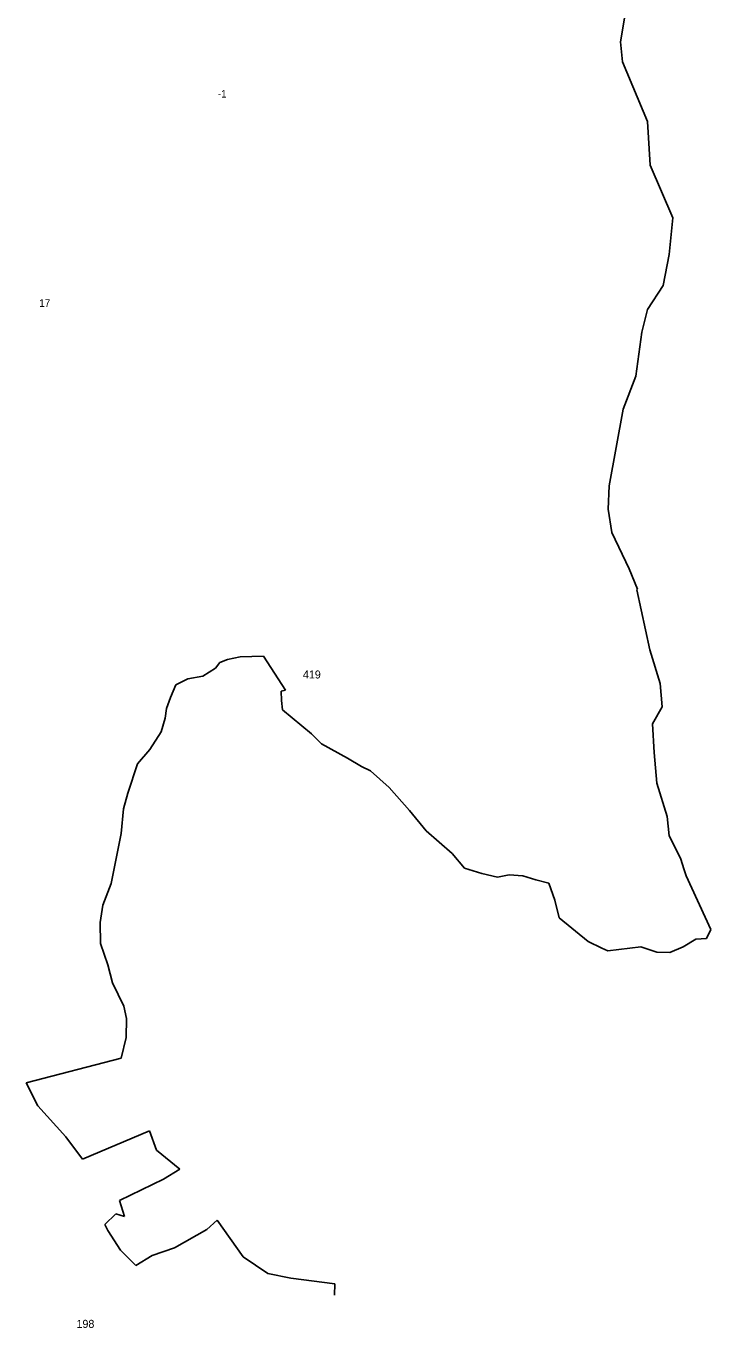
# Model space of a CAD drawing. Extents: x -779790 to -775735, y -971779 to -967735.
# Drawn here: x -777841 to -776814, y -971679 to -969727 of the extents above; entities that cross this region are included whole.
import ezdxf

# ---------------------------------------------------------------- set-up
doc = ezdxf.new("R2010")
doc.units = 0
for name, color, linetype in [('Vrstva 1', 7, 'Continuous'), ('Vrstva 15', 7, 'Continuous'), ('Vrstva 24', 7, 'Continuous')]:
    doc.layers.add(name, color=color, linetype=linetype)

msp = doc.modelspace()

# ---------------------------------------------------------------- linework, layer by layer
at = {"layer": 'Vrstva 1'}
for p, q in [((-776941.52, -969703.14), (-776949.64, -969750.41)), ((-776949.64, -969750.41), (-776946.93, -969780.45)), ((-776946.93, -969780.45), (-776909.02, -969870.08)), ((-776909.02, -969870.08), (-776905.09, -969935.33)), ((-776905.09, -969935.33), (-776871.35, -970014.61)), ((-776871.35, -970014.61), (-776876.53, -970069.51)), ((-776876.53, -970069.51), (-776885.88, -970115.8)), ((-776885.88, -970115.8), (-776909.27, -970151.75)), ((-776909.27, -970151.75), (-776917.65, -970185.98)), ((-776917.65, -970185.98), (-776926.76, -970251.71)), ((-776926.76, -970251.71), (-776945.96, -970301.2)), ((-776945.96, -970301.2), (-776966.89, -970416.18)), ((-776966.89, -970416.18), (-776968.36, -970451.39)), ((-776968.36, -970451.39), (-776962.94, -970486.6)), ((-776962.94, -970486.6), (-776936.84, -970541.01)), ((-776936.84, -970541.01), (-776924.04, -970571.29)), ((-776925.18, -970572.6), (-776924.04, -970571.29)), ((-777557.11, -970690), (-777550.31, -970681.51)), ((-777550.31, -970681.51), (-777538.76, -970677.09)), ((-777538.76, -970677.09), (-777520.06, -970673.01)), ((-777520.06, -970673.01), (-777485.06, -970671.99)), ((-777485.06, -970671.99), (-777452.1, -970722.97)), ((-777616.58, -970714.81), (-777598.57, -970705.98)), ((-777598.57, -970705.98), (-777575.8, -970701.9)), ((-777575.8, -970701.9), (-777557.11, -970690)), ((-777624.4, -970733.85), (-777616.58, -970714.81)), ((-777452.1, -970722.97), (-777458.39, -970724.55)), ((-777458.39, -970724.55), (-777457.87, -970738.27)), ((-777630.52, -970750.5), (-777624.4, -970733.85)), ((-777457.87, -970738.27), (-777456.51, -970752.2)), ((-777638.34, -970785.17), (-777632.22, -970764.77)), ((-777632.22, -970764.77), (-777630.52, -970750.5)), ((-777456.51, -970752.2), (-777413.01, -970788.57)), ((-777655.33, -970812.02), (-777638.34, -970785.17)), ((-777413.01, -970788.57), (-777398.06, -970803.18)), ((-777398.06, -970803.18), (-777358.97, -970824.93)), ((-777674.02, -970833.43), (-777655.33, -970812.02)), ((-777358.97, -970824.93), (-777337.9, -970837.51)), ((-777688.3, -970877.27), (-777674.02, -970833.43)), ((-777337.9, -970837.51), (-777324.65, -970843.96)), ((-777324.65, -970843.96), (-777296.78, -970868.77)), ((-777694.76, -970901.06), (-777688.3, -970877.27)), ((-777296.78, -970868.77), (-777265.85, -970903.44)), ((-777698.16, -970937.76), (-777694.76, -970901.06)), ((-777265.85, -970903.44), (-777241.04, -970934.03)), ((-777713.45, -971012.87), (-777698.16, -970937.76)), ((-777241.04, -970934.03), (-777202.29, -970968.01)), ((-777202.29, -970968.01), (-777183.6, -970989.77)), ((-777183.6, -970989.77), (-777157.77, -970997.92)), ((-777157.77, -970997.92), (-777134.32, -971003.36)), ((-777134.32, -971003.36), (-777116.65, -970999.96)), ((-777116.65, -970999.96), (-777095.91, -971001.32)), ((-777095.91, -971001.32), (-777076.54, -971007.44)), ((-777725.69, -971045.16), (-777713.45, -971012.87)), ((-777076.54, -971007.44), (-777057.17, -971012.2)), ((-777057.17, -971012.2), (-777048.33, -971038.03)), ((-777048.33, -971038.03), (-777041.88, -971064.2)), ((-777729.77, -971071.33), (-777725.69, -971045.16)), ((-777729.09, -971102.94), (-777729.77, -971071.33)), ((-777041.88, -971064.2), (-776998.03, -971099.54)), ((-777718.55, -971134.55), (-777729.09, -971102.94)), ((-777711.41, -971161.74), (-777718.55, -971134.55)), ((-777694.42, -971196.74), (-777711.41, -971161.74)), ((-777690.34, -971215.44), (-777694.42, -971196.74)), ((-777690.69, -971243.98), (-777690.34, -971215.44)), ((-777698.16, -971274.57), (-777690.69, -971243.98)), ((-777840.91, -971311.58), (-777698.16, -971274.57)), ((-777823.24, -971346.25), (-777840.91, -971311.58)), ((-777781.43, -971392.85), (-777823.24, -971346.25)), ((-777655.68, -971383.67), (-777756.28, -971426.49)), ((-777645.14, -971412.9), (-777655.68, -971383.67)), ((-777756.28, -971426.49), (-777781.43, -971392.85)), ((-777610.48, -971441.44), (-777645.14, -971412.9)), ((-777634.61, -971456.06), (-777610.48, -971441.44)), ((-777700.88, -971488), (-777634.61, -971456.06)), ((-777693.41, -971512.47), (-777700.88, -971488)), ((-777722.63, -971524.37), (-777706.32, -971508.4)), ((-777706.32, -971508.4), (-777693.41, -971512.47)), ((-777718.22, -971533.21), (-777722.63, -971524.37)), ((-777554.41, -971517.57), (-777570.04, -971531.85)), ((-777515.32, -971572.97), (-777554.41, -971517.57)), ((-777699.18, -971562.77), (-777718.22, -971533.21)), ((-777570.04, -971531.85), (-777618.3, -971559.38)), ((-777676.41, -971585.55), (-777699.18, -971562.77)), ((-777618.3, -971559.38), (-777651.94, -971570.59)), ((-777651.94, -971570.59), (-777676.41, -971585.55)), ((-777478.28, -971597.78), (-777515.32, -971572.97)), ((-777443.95, -971604.92), (-777478.28, -971597.78)), ((-777378.02, -971613.42), (-777443.95, -971604.92)), ((-777378.7, -971630.41), (-777378.02, -971613.42))]:
    msp.add_line(p, q, dxfattribs=at)
at = {"layer": 'Vrstva 15'}
for p, q in [((-776925.18, -970572.6), (-776905.76, -970662.12)), ((-776905.76, -970662.12), (-776890.42, -970712.98)), ((-776890.42, -970712.98), (-776887.19, -970747.7)), ((-776887.19, -970747.7), (-776901.73, -970773.53)), ((-776901.73, -970773.53), (-776899.3, -970816.32)), ((-776899.3, -970816.32), (-776895.27, -970862.34)), ((-776895.27, -970862.34), (-776879.93, -970912.4)), ((-776879.93, -970912.4), (-776876.7, -970941.46)), ((-776876.7, -970941.46), (-776859.74, -970974.56)), ((-776859.74, -970974.56), (-776854.09, -970992.32)), ((-776854.09, -970992.32), (-776851.26, -971001.41)), ((-776851.26, -971001.41), (-776814.13, -971081.74)), ((-776836.73, -971096.27), (-776855.7, -971107.98)), ((-776820.99, -971095.47), (-776836.73, -971096.27)), ((-776814.13, -971081.74), (-776820.99, -971095.47)), ((-776977.61, -971109.59), (-776998.03, -971099.54)), ((-776968.73, -971113.63), (-776977.61, -971109.59)), ((-776919.08, -971107.98), (-776968.73, -971113.63)), ((-776895.26, -971115.65), (-776919.08, -971107.98)), ((-776875.89, -971116.46), (-776895.26, -971115.65)), ((-776855.7, -971107.98), (-776875.89, -971116.46))]:
    msp.add_line(p, q, dxfattribs=at)

# ---------------------------------------------------------------- texts
at = {"layer": 'Vrstva 24'}
for s, height, p in [('-1', 11.25, (-777553.553, -969834.103)), ('17', 11.25, (-777821.347, -970147.913)), ('419', 12, (-777425.835, -970705.31)), ('198', 12, (-777765.291, -971679.23))]:
    msp.add_text(s, height=height, dxfattribs=at).set_placement(p)

doc.saveas('drawing.dxf')
